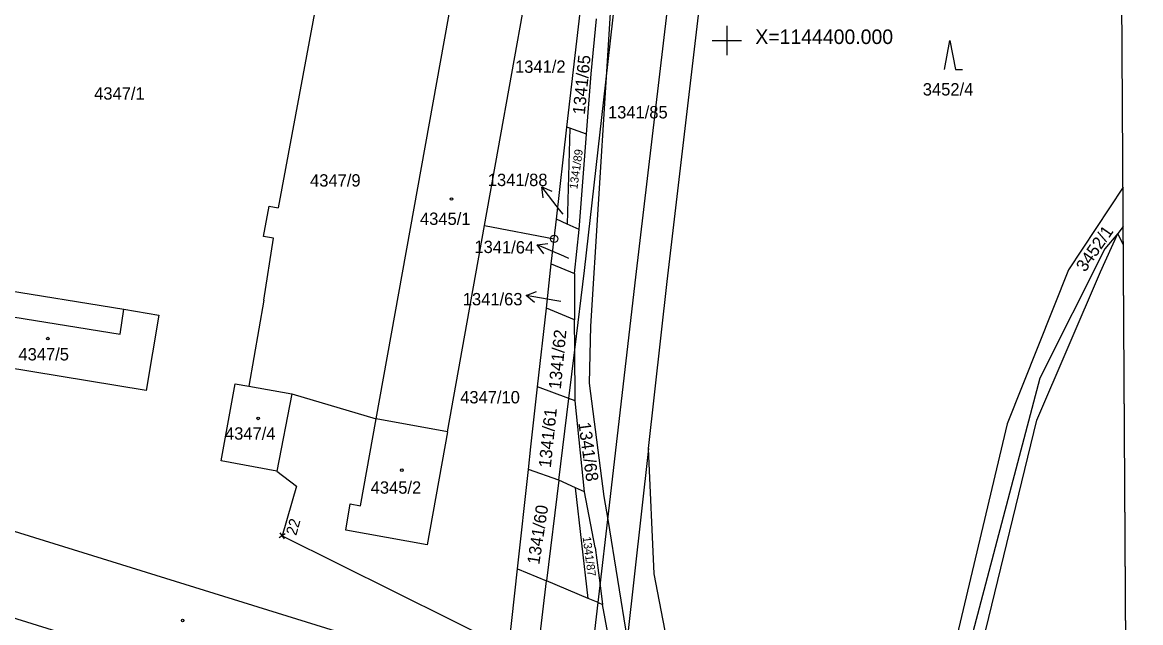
# Model space of a CAD drawing. Extents: x -735036 to -734743, y -1144813 to -1144181.
# Drawn here: x -734897 to -734743, y -1144480 to -1144397.5 of the extents above; entities that cross this region are included whole.
import ezdxf

# ---------------------------------------------------------------- set-up
doc = ezdxf.new("R2010")
doc.units = 0
for name, color, linetype in [('000_rozpiska', 7, 'Continuous'), ('BPEJ', 7, 'Continuous'), ('Groma (60)', 7, 'Continuous'), ('Katastr_HRANICE DRÁHY', 7, 'Continuous'), ('Katastr_Hranice parcel', 7, 'Continuous'), ('Katastr_Parcelní čísla', 7, 'Continuous'), ('Katastr_Slučkované čáry', 7, 'Continuous'), ('Katastr_Značky kultur', 7, 'Continuous'), ('Vrstva 7', 7, 'Continuous'), ('čtvercová síť', 7, 'Continuous')]:
    doc.layers.add(name, color=color, linetype=linetype)

# ---------------------------------------------------------------- blocks, each defined once
blk = doc.blocks.new('C691')
at = {"layer": 'Vrstva 7'}
for p, q in [((0, 0.5), (0, -0.5)), ((-0.5, 0), (0.5, 0))]:
    blk.add_line(p, q, dxfattribs=at)
blk = doc.blocks.new('POINT_DISPLAY')
for p, q in [((-0.35, -0.35), (0.35, 0.35)), ((-0.35, 0.35), (0.35, -0.35))]:
    blk.add_line(p, q)

msp = doc.modelspace()

# ---------------------------------------------------------------- linework, layer by layer
at = {"layer": '000_rozpiska'}
msp.add_line((-734743.05, -1144810.64), (-734746.94, -1144180.65), dxfattribs=at)
at = {"layer": 'BPEJ'}
msp.add_lwpolyline([(-734745.43, -1144425.57), (-734746.2, -1144426.51), (-734747.96, -1144428.65), (-734756.9, -1144446.43), (-734767.25, -1144485.5)], dxfattribs=at)
at = {"layer": 'Defpoints'}
msp.add_line((-734743.05, -1144810.64), (-734745.64, -1144390.65), dxfattribs=at)
at = {"layer": 'Katastr_HRANICE DRÁHY'}
for p, q in [((-734863.76, -1144426.93), (-734862.99, -1144422.76)), ((-734862.99, -1144422.76), (-734861.74, -1144422.99)), ((-734862.39, -1144427.18), (-734863.76, -1144426.93)), ((-734863.72, -1144435.68), (-734862.39, -1144427.18)), ((-734861.92, -1144459.22), (-734859.22, -1144461.28)), ((-734859.22, -1144461.28), (-734861.21, -1144468.1)), ((-734861.21, -1144468.1), (-734830.02, -1144483.57))]:
    msp.add_line(p, q, dxfattribs=at)
for points in [[(-734856.46, -1144394.74), (-734861.74, -1144422.99)], [(-734863.72, -1144435.68), (-734865.79, -1144447.52)], [(-734869.58, -1144457.79), (-734867.66, -1144447.19)], [(-734867.66, -1144447.19), (-734865.79, -1144447.52)], [(-734861.92, -1144459.22), (-734869.58, -1144457.79)]]:
    msp.add_lwpolyline(points, dxfattribs=at)
at = {"layer": 'Katastr_Hranice parcel'}
for p, q in [((-734833.36, -1144425.43), (-734827.31, -1144391.78)), ((-734822.01, -1144411.9), (-734820.19, -1144396.14)), ((-734823.77, -1144427.26), (-734823.46, -1144424.57)), ((-734830.02, -1144483.57), (-734828.81, -1144472.64))]:
    msp.add_line(p, q, dxfattribs=at)
for points in [[(-734848.25, -1144452.02), (-734837.31, -1144391.22)], [(-734815.76, -1144391.08), (-734816.67, -1144405.73)], [(-734808.21, -1144433.11), (-734803.24, -1144391.01)], [(-734818.66, -1144404.58), (-734817.92, -1144397.01)], [(-734819.31, -1144412.88), (-734818.66, -1144404.58)], [(-734816.67, -1144405.73), (-734818.75, -1144439.28)], [(-734823.46, -1144424.57), (-734822.01, -1144411.9)], [(-734821.62, -1144412.04), (-734822.01, -1144411.9)], [(-734821.62, -1144412.04), (-734821.97, -1144425.24)], [(-734819.31, -1144412.88), (-734821.62, -1144412.04)], [(-734820.32, -1144425.99), (-734819.31, -1144412.88)], [(-734745.46, -1144420.16), (-734752.99, -1144431.55)], [(-734821.97, -1144425.24), (-734823.46, -1144424.57)], [(-734838.46, -1144453.82), (-734833.36, -1144425.43)], [(-734833.36, -1144425.43), (-734823.77, -1144427.26)], [(-734820.32, -1144425.99), (-734821.97, -1144425.24)], [(-734820.97, -1144432.03), (-734820.32, -1144425.99)], [(-734748.56, -1144431.79), (-734746.2, -1144426.51)], [(-734746.2, -1144426.51), (-734747.96, -1144428.65)], [(-734745.43, -1144425.57), (-734746.2, -1144426.51)], [(-734745.41, -1144428.13), (-734746.2, -1144426.51)], [(-734824.17, -1144430.72), (-734823.77, -1144427.26)], [(-734747.96, -1144428.65), (-734756.9, -1144446.43)], [(-734824.84, -1144436.79), (-734824.17, -1144430.72)], [(-734824.17, -1144430.72), (-734820.97, -1144432.03)], [(-734820.97, -1144432.03), (-734820.97, -1144438.4)], [(-734752.99, -1144431.55), (-734761.43, -1144452.7)], [(-734757.32, -1144452.22), (-734748.56, -1144431.79)], [(-734900.62, -1144434.11), (-734883, -1144436.95)], [(-734810.79, -1144456.08), (-734808.21, -1144433.11)], [(-734883, -1144436.95), (-734878.19, -1144437.75)], [(-734826.04, -1144447.62), (-734824.84, -1144436.79)], [(-734820.97, -1144438.4), (-734824.84, -1144436.79)], [(-734878.19, -1144437.75), (-734879.9, -1144448.12)], [(-734820.94, -1144442.53), (-734820.97, -1144438.4)], [(-734818.75, -1144439.28), (-734818.94, -1144447.13)], [(-734879.9, -1144448.12), (-734907.55, -1144443.6)], [(-734820.88, -1144449.56), (-734820.94, -1144442.53)], [(-734756.9, -1144446.43), (-734767.25, -1144485.5)], [(-734865.79, -1144447.52), (-734859.89, -1144448.56)], [(-734826.96, -1144455.87), (-734826.04, -1144447.62)], [(-734821.75, -1144449.23), (-734826.04, -1144447.62)], [(-734818.94, -1144447.13), (-734816.91, -1144462.68)], [(-734859.89, -1144448.56), (-734861.92, -1144459.22)], [(-734859.89, -1144448.56), (-734848.25, -1144452.02)], [(-734820.88, -1144449.56), (-734821.75, -1144449.23)], [(-734819.57, -1144462.07), (-734820.88, -1144449.56)], [(-734850.4, -1144463.96), (-734848.25, -1144452.02)], [(-734838.46, -1144453.82), (-734848.25, -1144452.02)], [(-734761.43, -1144452.7), (-734769.6, -1144487.14)], [(-734764.76, -1144482.73), (-734757.32, -1144452.22)], [(-734838.46, -1144453.82), (-734841.25, -1144469.34)], [(-734827.3, -1144458.97), (-734826.96, -1144455.87)], [(-734810.79, -1144456.08), (-734813.74, -1144482.35)], [(-734810.02, -1144473.32), (-734810.79, -1144456.08)], [(-734828.81, -1144472.64), (-734827.3, -1144458.97)], [(-734823.12, -1144460.47), (-734827.3, -1144458.97)], [(-734820.84, -1144461.5), (-734823.12, -1144460.47)], [(-734819.57, -1144462.07), (-734820.84, -1144461.5)], [(-734819.07, -1144476.7), (-734820.84, -1144461.5)], [(-734818.11, -1144469.69), (-734819.57, -1144462.07)], [(-734816.91, -1144462.68), (-734816.4, -1144465.87)], [(-734852.45, -1144467.31), (-734851.86, -1144463.72)], [(-734851.86, -1144463.72), (-734850.4, -1144463.96)], [(-734902.72, -1144466.02), (-734842.51, -1144484.69)], [(-734816.4, -1144465.87), (-734813.74, -1144482.35)], [(-734841.25, -1144469.34), (-734852.45, -1144467.31)], [(-734818.11, -1144469.69), (-734817.45, -1144474.93)], [(-734828.81, -1144472.64), (-734824.8, -1144474.27)], [(-734819.07, -1144476.7), (-734824.8, -1144474.27)], [(-734800.88, -1144520.61), (-734810.02, -1144473.32)], [(-734817.45, -1144474.93), (-734817.12, -1144477.54)], [(-734850.95, -1144494.07), (-734906.11, -1144476.96)], [(-734817.72, -1144477.28), (-734819.07, -1144476.7)], [(-734817.72, -1144477.28), (-734817.12, -1144477.54)], [(-734814.66, -1144490.59), (-734817.12, -1144477.54)]]:
    msp.add_lwpolyline(points, dxfattribs=at)
at = {"layer": 'Katastr_Parcelní čísla'}
for p, q in [((-734825.26, -1144421.61), (-734825.46, -1144420.12)), ((-734822.54, -1144423.89), (-734823.01, -1144423.28)), ((-734825.21, -1144429.31), (-734826.12, -1144428.11)), ((-734821.74, -1144429.95), (-734822.43, -1144429.66)), ((-734826.48, -1144436), (-734827.63, -1144435.04)), ((-734822.84, -1144435.88), (-734823.69, -1144435.73))]:
    msp.add_line(p, q, dxfattribs=at)
for points in [[(-734823.01, -1144423.28), (-734825.46, -1144420.12), (-734824.07, -1144420.69)], [(-734822.43, -1144429.66), (-734826.12, -1144428.11), (-734824.63, -1144427.92)], [(-734823.69, -1144435.73), (-734827.63, -1144435.04), (-734826.22, -1144434.52)]]:
    msp.add_lwpolyline(points, dxfattribs=at)
at = {"layer": 'Katastr_Slučkované čáry'}
for points in [[(-734816.67, -1144405.73), (-734815.01, -1144391.08)], [(-734812.53, -1144432.52), (-734807.63, -1144391.03)], [(-734819.61, -1144431.61), (-734816.67, -1144405.73)], [(-734820.94, -1144442.53), (-734819.61, -1144431.61)], [(-734816.4, -1144465.87), (-734812.53, -1144432.52)], [(-734883.5, -1144440.36), (-734883, -1144436.95)], [(-734901.18, -1144437.52), (-734883.5, -1144440.36)], [(-734821.75, -1144449.23), (-734820.94, -1144442.53)], [(-734823.12, -1144460.47), (-734821.75, -1144449.23)], [(-734823.12, -1144460.47), (-734824.8, -1144474.27)], [(-734817.45, -1144474.93), (-734816.4, -1144465.87)], [(-734825.84, -1144482.82), (-734824.8, -1144474.27)], [(-734817.72, -1144477.28), (-734817.45, -1144474.93)], [(-734819.59, -1144493.44), (-734817.72, -1144477.28)]]:
    msp.add_lwpolyline(points, dxfattribs=at)
at = {"layer": 'Katastr_Značky kultur'}
msp.add_line((-734823.82, -1144427.26), (-734823.72, -1144427.26), dxfattribs=at)
msp.add_lwpolyline([(-734770.05, -1144403.98), (-734769.3, -1144399.98), (-734768.55, -1144403.98), (-734767.55, -1144403.98)], dxfattribs=at)
for centre, radius in [((-734837.9, -1144421.79), 0.175), ((-734823.77, -1144427.26), 0.499), ((-734893.45, -1144440.98), 0.175), ((-734864.51, -1144451.96), 0.175), ((-734844.73, -1144459.08), 0.175), ((-734874.9, -1144479.74), 0.175)]:
    msp.add_circle(centre, radius, dxfattribs=at)

# ---------------------------------------------------------------- block references
at = {"layer": 'Groma (60)', "rotation": -98.65482414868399}
msp.add_blockref('POINT_DISPLAY', (-734861.21, -1144468.1), dxfattribs=at)
at = {"layer": 'čtvercová síť', "xscale": 4, "yscale": 4}
msp.add_blockref('C691', (-734800, -1144400), dxfattribs=at)

# ---------------------------------------------------------------- texts
at = {"layer": 'Groma (60)'}
msp.add_text('22', height=1.5, rotation=74.2209, dxfattribs=at).set_placement((-734859.27, -1144468.14))
at = {"layer": 'Katastr_Parcelní čísla'}
for s, p in [('1341/2', (-734829.15, -1144404.44)), ('4347/1', (-734887.08, -1144408.13)), ('3452/4', (-734773.03, -1144407.56)), ('1341/85', (-734816.36, -1144410.71)), ('4347/9', (-734857.36, -1144420.08)), ('1341/88', (-734832.9, -1144420.01)), ('4345/1', (-734842.23, -1144425.35)), ('1341/63', (-734836.34, -1144436.41)), ('4347/5', (-734897.5, -1144443.99)), ('4347/10', (-734836.7, -1144449.89)), ('4347/4', (-734869.07, -1144454.88)), ('4345/2', (-734849.02, -1144462.31))]:
    msp.add_text(s, height=1.7, dxfattribs=at).set_placement(p)
for s, height, rotation, p in [('1341/65', 1.7, 84.3541, (-734819.55, -1144410.25)), ('1341/89', 1.14, 81.8181, (-734820.58, -1144420.49)), ('3452/1', 1.7, 55.1362, (-734750.68, -1144431.93)), ('1341/64', 1.7, 359.3069, (-734834.75, -1144429.2)), ('1341/62', 1.7, 84.5309, (-734822.85, -1144448.01)), ('1341/61', 1.7, 84.0626, (-734824.23, -1144458.8)), ('1341/68', 1.7, 277.952, (-734820.45, -1144452.58)), ('1341/60', 1.7, 81.2094, (-734825.82, -1144472.13)), ('1341/87', 1.14, 277.4791, (-734819.85, -1144468.28))]:
    msp.add_text(s, height=height, rotation=rotation, dxfattribs=at).set_placement(p)
at = {"layer": 'čtvercová síť'}
msp.add_text('X=1144400.000', height=2, dxfattribs=at).set_placement((-734796.08, -1144400.48))

doc.saveas('drawing.dxf')
